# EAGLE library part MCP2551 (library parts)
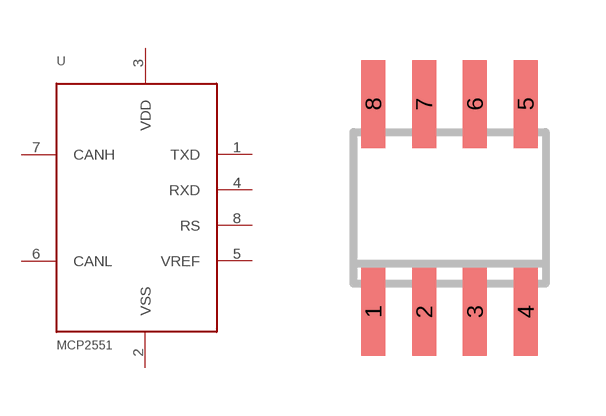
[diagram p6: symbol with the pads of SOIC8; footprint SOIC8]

Designator prefix -

## MCP2551SOIC8  [SOIC8]
1  TXD
2  VSS
3  VDD
4  RXD
5  VREF
6  CANL
7  CANH
8  RS

## Footprint SOIC8 (pad centres in mm)
Small Outline IC
smd 0.6 x 2.2: 1 -1.905,-2.6; 2 -0.635,-2.6; 3 0.635,-2.6; 4 1.905,-2.6; 5 1.905,2.6; 6 0.635,2.6; 7 -0.635,2.6; 8 -1.905,2.6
